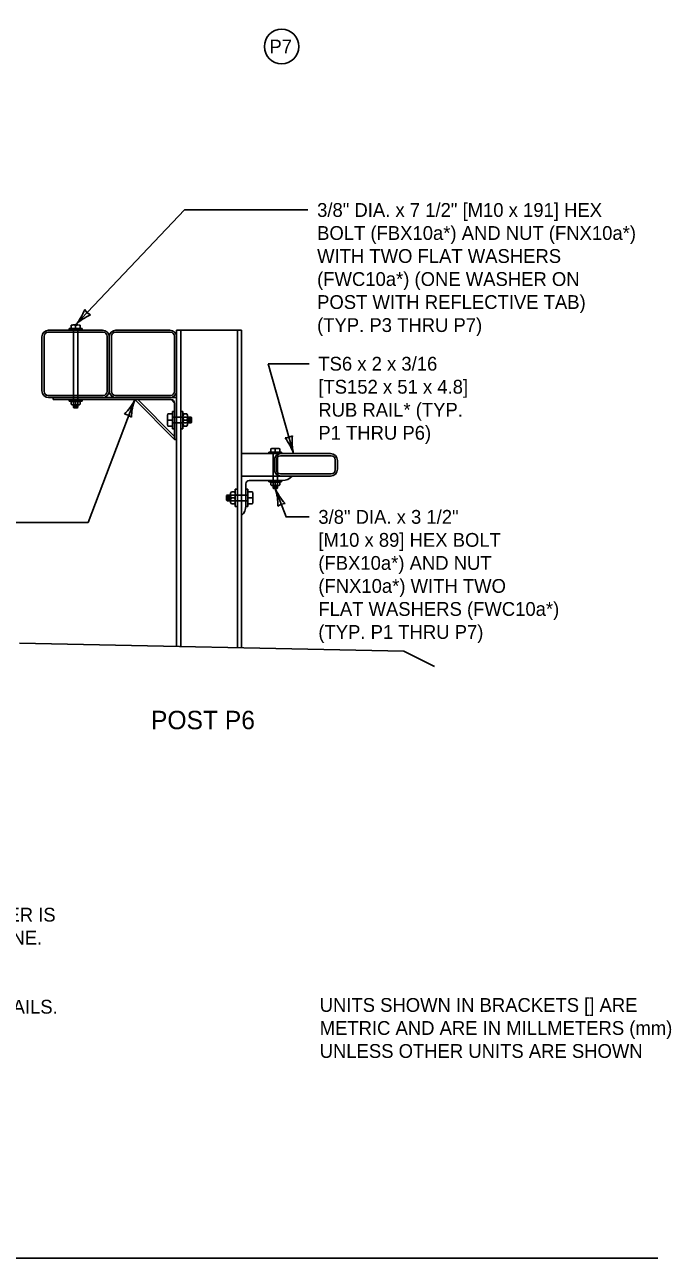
# Model space of a CAD drawing. Extents: x 49983 to 50021, y 49963.5 to 50011.4.
# Drawn here: x 50011.34 to 50014.05, y 49987.8 to 49993.16 of the extents above; entities that cross this region are included whole.
import ezdxf

# ---------------------------------------------------------------- set-up
doc = ezdxf.new("R2010")
doc.units = 0
for name, color, linetype in [('Level 1', 7, 'Continuous'), ('Level 10', 7, 'Continuous'), ('Level 2', 7, 'Continuous'), ('Level 3', 7, 'Continuous')]:
    doc.layers.add(name, color=color, linetype=linetype)

msp = doc.modelspace()

# ---------------------------------------------------------------- linework, layer by layer
at = {"layer": 'Level 1'}
for p, q in [((50011.539, 49991.8523), (50011.539, 49991.8375)), ((50011.5489, 49991.8534), (50011.5686, 49991.8534)), ((50011.5587, 49991.8523), (50011.5587, 49991.8375)), ((50011.5785, 49991.8523), (50011.5785, 49991.8375)), ((50011.4123, 49991.8016), (50011.4123, 49991.5674)), ((50011.4215, 49991.8041), (50011.4215, 49991.5648)), ((50011.4391, 49991.8217), (50011.6784, 49991.8217)), ((50011.4416, 49991.8309), (50011.6758, 49991.8309)), ((50011.5305, 49991.8375), (50011.5866, 49991.8375)), ((50011.5305, 49991.8375), (50011.5305, 49991.8309)), ((50011.5496, 49991.5472), (50011.5496, 49991.8217)), ((50011.5679, 49991.5472), (50011.5679, 49991.8217)), ((50011.5866, 49991.8375), (50011.5866, 49991.8309)), ((50011.696, 49991.8041), (50011.696, 49991.5648)), ((50011.7051, 49991.8016), (50011.7051, 49991.5674)), ((50011.7051, 49991.8016), (50011.7051, 49991.5674)), ((50011.7143, 49991.8041), (50011.7143, 49991.5648)), ((50011.7319, 49991.8217), (50011.9712, 49991.8217)), ((50011.7344, 49991.8309), (50011.9687, 49991.8309)), ((50011.9888, 49991.8041), (50011.9888, 49991.5648)), ((50011.998, 49991.8309), (50011.998, 49991.5381)), ((50012.2802, 49991.8309), (50011.998, 49991.8309)), ((50011.998, 49990.4567), (50011.998, 49991.8309)), ((50012.016, 49990.4563), (50012.016, 49991.8309)), ((50012.2622, 49990.4514), (50012.2622, 49991.8309)), ((50012.2802, 49990.451), (50012.2802, 49991.8309)), ((50011.4391, 49991.5472), (50011.6784, 49991.5472)), ((50011.4416, 49991.5381), (50011.7051, 49991.5381)), ((50011.4611, 49991.5381), (50011.998, 49991.5381)), ((50011.4611, 49991.5289), (50011.4611, 49991.5381)), ((50011.4611, 49991.5289), (50011.9742, 49991.5289)), ((50011.5309, 49991.5223), (50011.5309, 49991.5289)), ((50011.5869, 49991.5223), (50011.5869, 49991.5289)), ((50011.7051, 49991.5381), (50011.998, 49991.5381)), ((50011.7319, 49991.5472), (50011.9712, 49991.5472)), ((50011.9888, 49991.3563), (50011.8162, 49991.5289)), ((50011.8291, 49991.5289), (50011.9888, 49991.3692)), ((50011.9742, 49991.5289), (50011.9888, 49991.5143)), ((50011.5869, 49991.5223), (50011.5309, 49991.5223)), ((50011.539, 49991.5094), (50011.539, 49991.5193)), ((50011.5686, 49991.5063), (50011.5489, 49991.5063)), ((50011.5496, 49991.4955), (50011.5496, 49991.5063)), ((50011.5679, 49991.4955), (50011.5496, 49991.4955)), ((50011.5496, 49991.4955), (50011.5514, 49991.4937)), ((50011.5514, 49991.4937), (50011.5661, 49991.4937)), ((50011.5522, 49991.5038), (50011.5651, 49991.5038)), ((50011.5522, 49991.502), (50011.5651, 49991.502)), ((50011.5522, 49991.5001), (50011.5651, 49991.5001)), ((50011.5522, 49991.4983), (50011.5651, 49991.4983)), ((50011.5587, 49991.5193), (50011.5587, 49991.5094)), ((50011.5679, 49991.4955), (50011.5661, 49991.4937)), ((50011.5679, 49991.4955), (50011.5679, 49991.5063)), ((50011.5785, 49991.5094), (50011.5785, 49991.5193)), ((50011.98, 49991.4026), (50011.98, 49991.4778)), ((50011.98, 49991.4778), (50011.9888, 49991.4778)), ((50011.9888, 49991.5143), (50011.9888, 49991.3563)), ((50012.0248, 49991.4778), (50012.016, 49991.4778)), ((50012.0248, 49991.4026), (50012.0248, 49991.4778)), ((50011.9585, 49991.4272), (50011.9585, 49991.4537)), ((50011.9601, 49991.4669), (50011.98, 49991.4669)), ((50011.9601, 49991.4404), (50011.98, 49991.4404)), ((50012.0422, 49991.4669), (50012.0289, 49991.4669)), ((50012.0289, 49991.4404), (50012.0422, 49991.4404)), ((50012.0463, 49991.4272), (50012.0463, 49991.4537)), ((50012.0608, 49991.4527), (50012.0463, 49991.4527)), ((50012.0608, 49991.4282), (50012.0463, 49991.4282)), ((50012.0497, 49991.4317), (50012.0497, 49991.449)), ((50012.0522, 49991.4317), (50012.0522, 49991.449)), ((50012.0546, 49991.4317), (50012.0546, 49991.449)), ((50012.0571, 49991.4317), (50012.0571, 49991.449)), ((50012.0608, 49991.4527), (50012.0608, 49991.4282)), ((50012.0608, 49991.4527), (50012.0633, 49991.4503)), ((50012.0608, 49991.4282), (50012.0633, 49991.4306)), ((50012.0633, 49991.4306), (50012.0633, 49991.4503)), ((50011.9601, 49991.4139), (50011.98, 49991.4139)), ((50011.98, 49991.4026), (50011.9888, 49991.4026)), ((50012.0248, 49991.4026), (50012.016, 49991.4026)), ((50012.0422, 49991.4139), (50012.0289, 49991.4139)), ((50011.998, 49991.3563), (50011.9888, 49991.3563)), ((50012.4071, 49991.316), (50012.4071, 49991.3012)), ((50012.417, 49991.3172), (50012.4368, 49991.3172)), ((50012.4269, 49991.316), (50012.4269, 49991.3012)), ((50012.4466, 49991.316), (50012.4466, 49991.3012)), ((50012.2802, 49991.2946), (50012.6678, 49991.2946)), ((50012.3987, 49991.3012), (50012.4547, 49991.3012)), ((50012.3987, 49991.3012), (50012.3987, 49991.2946)), ((50012.4229, 49991.2263), (50012.4229, 49991.2653)), ((50012.432, 49991.2237), (50012.432, 49991.2679)), ((50012.436, 49991.2126), (50012.436, 49991.2791)), ((50012.4496, 49991.2855), (50012.6704, 49991.2855)), ((50012.4547, 49991.3012), (50012.4547, 49991.2946)), ((50012.688, 49991.2679), (50012.688, 49991.2237)), ((50012.6971, 49991.2653), (50012.6971, 49991.2263)), ((50012.4496, 49991.2061), (50012.6704, 49991.2061)), ((50012.2802, 49991.197), (50012.6678, 49991.197)), ((50012.4998, 49991.197), (50012.2802, 49991.197)), ((50012.2991, 49991.0681), (50012.2991, 49991.1634)), ((50012.4579, 49991.1781), (50012.3138, 49991.1781)), ((50012.3987, 49991.1715), (50012.3987, 49991.1781)), ((50012.3987, 49991.1715), (50012.4547, 49991.1715)), ((50012.4071, 49991.1585), (50012.4071, 49991.1684)), ((50012.417, 49991.1555), (50012.4368, 49991.1555)), ((50012.4177, 49991.1446), (50012.4177, 49991.1555)), ((50012.4204, 49991.1529), (50012.4333, 49991.1529)), ((50012.4204, 49991.1511), (50012.4333, 49991.1511)), ((50012.4204, 49991.1493), (50012.4333, 49991.1493)), ((50012.4269, 49991.1684), (50012.4269, 49991.1585)), ((50012.436, 49991.1446), (50012.436, 49991.1555)), ((50012.4466, 49991.1585), (50012.4466, 49991.1684)), ((50012.4547, 49991.1715), (50012.4547, 49991.1781)), ((50012.2173, 49991.1146), (50012.2149, 49991.1121)), ((50012.2149, 49991.0925), (50012.2149, 49991.1121)), ((50012.2173, 49991.1146), (50012.2173, 49991.09)), ((50012.2173, 49991.1146), (50012.2319, 49991.1146)), ((50012.221, 49991.0936), (50012.221, 49991.1109)), ((50012.2235, 49991.0936), (50012.2235, 49991.1109)), ((50012.226, 49991.0936), (50012.226, 49991.1109)), ((50012.2285, 49991.0936), (50012.2285, 49991.1109)), ((50012.2319, 49991.089), (50012.2319, 49991.1156)), ((50012.236, 49991.1288), (50012.2492, 49991.1288)), ((50012.2492, 49991.1023), (50012.236, 49991.1023)), ((50012.2533, 49991.0644), (50012.2533, 49991.1396)), ((50012.2533, 49991.1396), (50012.2622, 49991.1396)), ((50012.308, 49991.1396), (50012.2991, 49991.1396)), ((50012.308, 49991.0644), (50012.308, 49991.1396)), ((50012.3278, 49991.1288), (50012.308, 49991.1288)), ((50012.3278, 49991.1023), (50012.308, 49991.1023)), ((50012.3294, 49991.0891), (50012.3294, 49991.1156)), ((50012.436, 49991.1446), (50012.4177, 49991.1446)), ((50012.4177, 49991.1446), (50012.4196, 49991.1428)), ((50012.4196, 49991.1428), (50012.4342, 49991.1428)), ((50012.4204, 49991.1474), (50012.4333, 49991.1474)), ((50012.436, 49991.1446), (50012.4342, 49991.1428)), ((50012.2173, 49991.09), (50012.2149, 49991.0925)), ((50012.2173, 49991.09), (50012.2319, 49991.09)), ((50012.236, 49991.0758), (50012.2492, 49991.0758)), ((50012.2533, 49991.0644), (50012.2622, 49991.0644)), ((50012.308, 49991.0644), (50012.2991, 49991.0644)), ((50012.3278, 49991.0758), (50012.308, 49991.0758)), ((50011.3147, 49990.4704), (50012.9857, 49990.4369)), ((50012.9857, 49990.4369), (50013.1197, 49990.3699))]:
    msp.add_line(p, q, dxfattribs=at)
msp.add_lwpolyline([(49999.3835, 49998.9992), (50016.7501, 49998.9992), (50016.7501, 49987.7988), (49999.3835, 49987.7988)], close=True, dxfattribs=at)
for centre, radius, start, end in [((50011.5489, 49991.812), 0.0415, 76.2307, 103.7693), ((50011.5686, 49991.812), 0.0415, 76.2307, 103.7693), ((50011.4416, 49991.8016), 0.0293, 90, 180), ((50011.4391, 49991.8041), 0.0176, 90, 180), ((50011.6758, 49991.8016), 0.0293, 0, 90), ((50011.6784, 49991.8041), 0.0176, 0, 90), ((50011.7344, 49991.8016), 0.0293, 90, 180), ((50011.7319, 49991.8041), 0.0176, 90, 180), ((50011.9687, 49991.8016), 0.0293, 0, 90), ((50011.9712, 49991.8041), 0.0176, 0, 90), ((50011.4416, 49991.5674), 0.0293, 180, 270), ((50011.4391, 49991.5648), 0.0176, 180, 270), ((50011.6758, 49991.5674), 0.0293, 270, 0), ((50011.6784, 49991.5648), 0.0176, 270, 0), ((50011.7344, 49991.5674), 0.0293, 180, 270), ((50011.7319, 49991.5648), 0.0176, 180, 270), ((50011.9687, 49991.5674), 0.0293, 270, 0), ((50011.9712, 49991.5648), 0.0176, 270, 0), ((50011.9742, 49991.5143), 0.0146, 0, 90), ((50011.5489, 49991.5048), 0.0175, 55.616, 124.384), ((50011.5489, 49991.5238), 0.0175, 235.616, 304.384), ((50011.5686, 49991.5048), 0.0175, 55.616, 124.384), ((50011.5686, 49991.5238), 0.0175, 235.616, 304.384), ((50012.0142, 49991.4537), 0.0557, 166.2307, 193.7693), ((50012.0142, 49991.4272), 0.0557, 166.2307, 193.7693), ((50012.0483, 49991.4537), 0.0235, 145.616, 214.384), ((50012.0483, 49991.4272), 0.0235, 145.616, 214.384), ((50012.0228, 49991.4537), 0.0235, 325.616, 34.384), ((50012.0228, 49991.4272), 0.0235, 325.616, 34.384), ((50012.417, 49991.2757), 0.0415, 76.2307, 103.7693), ((50012.4368, 49991.2757), 0.0415, 76.2307, 103.7693), ((50012.4522, 49991.2653), 0.0293, 90, 180), ((50012.4496, 49991.2679), 0.0176, 90, 180), ((50012.6678, 49991.2653), 0.0293, 0, 90), ((50012.6704, 49991.2679), 0.0176, 0, 90), ((50012.4522, 49991.2263), 0.0293, 180, 270), ((50012.4496, 49991.2237), 0.0176, 180, 270), ((50012.6678, 49991.2263), 0.0293, 270, 0), ((50012.6704, 49991.2237), 0.0176, 270, 0), ((50012.3138, 49991.1634), 0.0146, 90, 180), ((50012.417, 49991.154), 0.0175, 55.616, 124.384), ((50012.417, 49991.173), 0.0175, 235.616, 304.384), ((50012.4368, 49991.154), 0.0175, 55.616, 124.384), ((50012.4368, 49991.173), 0.0175, 235.616, 304.384), ((50012.4597, 49991.2299), 0.0518, 268.0404, 320.6703), ((50012.2554, 49991.1156), 0.0235, 145.616, 214.384), ((50012.2554, 49991.089), 0.0235, 145.616, 214.384), ((50012.2299, 49991.1156), 0.0235, 325.616, 34.384), ((50012.2299, 49991.089), 0.0235, 325.616, 34.384), ((50012.2738, 49991.1156), 0.0557, 346.2307, 13.7693), ((50012.2738, 49991.089), 0.0557, 346.2307, 13.7693), ((50012.2473, 49991.0663), 0.0518, 309.3297, 1.9596)]:
    msp.add_arc(centre, radius, start, end, dxfattribs=at)
at = {"layer": 'Level 10'}
for p, q in [((50011.5496, 49991.8217), (50011.5496, 49991.8375)), ((50011.5679, 49991.8217), (50011.5679, 49991.8375)), ((50011.5496, 49991.5472), (50011.5496, 49991.5063)), ((50011.5679, 49991.5472), (50011.5679, 49991.5063)), ((50011.98, 49991.4527), (50012.0463, 49991.4527)), ((50011.98, 49991.4282), (50012.0463, 49991.4282)), ((50012.4177, 49991.3012), (50012.4177, 49991.1555)), ((50012.436, 49991.2791), (50012.436, 49991.3012)), ((50012.436, 49991.2126), (50012.436, 49991.1555)), ((50012.308, 49991.1146), (50012.2319, 49991.1146)), ((50012.308, 49991.09), (50012.2319, 49991.09))]:
    msp.add_line(p, q, dxfattribs=at)
at = {"layer": 'Level 2'}
msp.add_circle((50012.4545, 49993.0629), 0.075, dxfattribs=at)
at = {"layer": 'Level 3'}
for p, q in [((50011.5587, 49991.8534), (50012.0316, 49992.3529)), ((50012.5689, 49992.3529), (50012.0316, 49992.3529)), ((50012.5742, 49991.685), (50012.3958, 49991.685)), ((50012.5062, 49991.2946), (50012.3958, 49991.685)), ((50011.8162, 49991.5289), (50011.6129, 49990.9949)), ((50011.1502, 49990.9949), (50011.6129, 49990.9949))]:
    msp.add_line(p, q, dxfattribs=at)
msp.add_lwpolyline([(50012.4269, 49991.1428), (50012.4742, 49991.0197), (50012.5742, 49991.0197)], dxfattribs=at)
for centre, radius, start, end in [((50011.3818, 49992.0051), 0.233, 319.3938, 338.6437), ((50011.6469, 49991.9466), 0.0548, 208.7053, 244.4277), ((50011.7137, 49991.6941), 0.2223, 114.0225, 134.206), ((50011.6157, 49991.625), 0.2223, 314.2217, 334.4052), ((50012.0345, 49991.4477), 0.233, 159.593, 178.8429), ((50011.7656, 49991.4111), 0.0548, 48.9045, 84.6269), ((50012.4713, 49991.418), 0.0548, 267.926, 303.6483), ((50012.2854, 49991.2203), 0.233, 18.6145, 37.8643), ((50012.7225, 49991.3463), 0.2223, 173.2432, 193.4267), ((50012.2162, 49991.0717), 0.2223, 358.476, 18.6595), ((50012.64, 49991.237), 0.233, 203.8473, 223.0971), ((50012.4729, 49991.0231), 0.0548, 93.1588, 128.8811)]:
    msp.add_arc(centre, radius, start, end, dxfattribs=at)

# ---------------------------------------------------------------- texts
at = {"layer": 'Level 2'}
for s, height, p in [('P7', 0.06, (50012.4014, 49993.033)), ('3/8" DIA. x 7 1/2" [M10 x 191] HEX ', 0.06, (50012.6089, 49992.3229)), ('BOLT (FBX10a*) AND NUT (FNX10a*)', 0.06, (50012.6089, 49992.2229)), ('WITH TWO FLAT WASHERS', 0.06, (50012.6089, 49992.1229)), ('(FWC10a*) (ONE WASHER ON', 0.06, (50012.6089, 49992.0229)), ('POST WITH REFLECTIVE TAB)', 0.06, (50012.6089, 49991.9229)), ('(TYP. P3 THRU P7)', 0.06, (50012.6089, 49991.8229)), ('TS6 x 2 x 3/16', 0.06, (50012.6142, 49991.655)), ('[TS152 x 51 x 4.8]  ', 0.06, (50012.6142, 49991.555)), ('RUB RAIL* (TYP. ', 0.06, (50012.6142, 49991.455)), ('P1 THRU P6)', 0.06, (50012.6142, 49991.355)), ('3/8" DIA. x 3 1/2"', 0.06, (50012.6142, 49990.9897)), ('[M10 x 89] HEX BOLT', 0.06, (50012.6142, 49990.8897)), ('(FBX10a*) AND NUT ', 0.06, (50012.6142, 49990.7897)), ('(FNX10a*) WITH TWO ', 0.06, (50012.6142, 49990.6897)), ('FLAT WASHERS (FWC10a*) ', 0.06, (50012.6142, 49990.5897)), ('(TYP. P1 THRU P7)', 0.06, (50012.6142, 49990.4897)), ('POST P6', 0.08, (50011.8867, 49990.0973)), ('WIDENING IS REQUIRED IF FINISHED SHOULDER IS', 0.06, (50009.4614, 49989.2617)), ('LESS THAN 2\'-0" [0.6 m] FROM THE TRAFFIC LANE.', 0.06, (50009.4614, 49989.1617)), ('BOX BEAM GUARDRAIL AND ASSOCIATED DETAILS.', 0.06, (50009.4614, 49988.8617)), ('UNITS SHOWN IN BRACKETS [] ARE', 0.06, (50012.62, 49988.8694)), ('METRIC AND ARE IN MILLMETERS (mm)', 0.06, (50012.62, 49988.7694)), ('UNLESS OTHER UNITS ARE SHOWN', 0.06, (50012.62, 49988.6694))]:
    msp.add_text(s, height=height, dxfattribs=at).set_placement(p)

doc.saveas('drawing.dxf')
